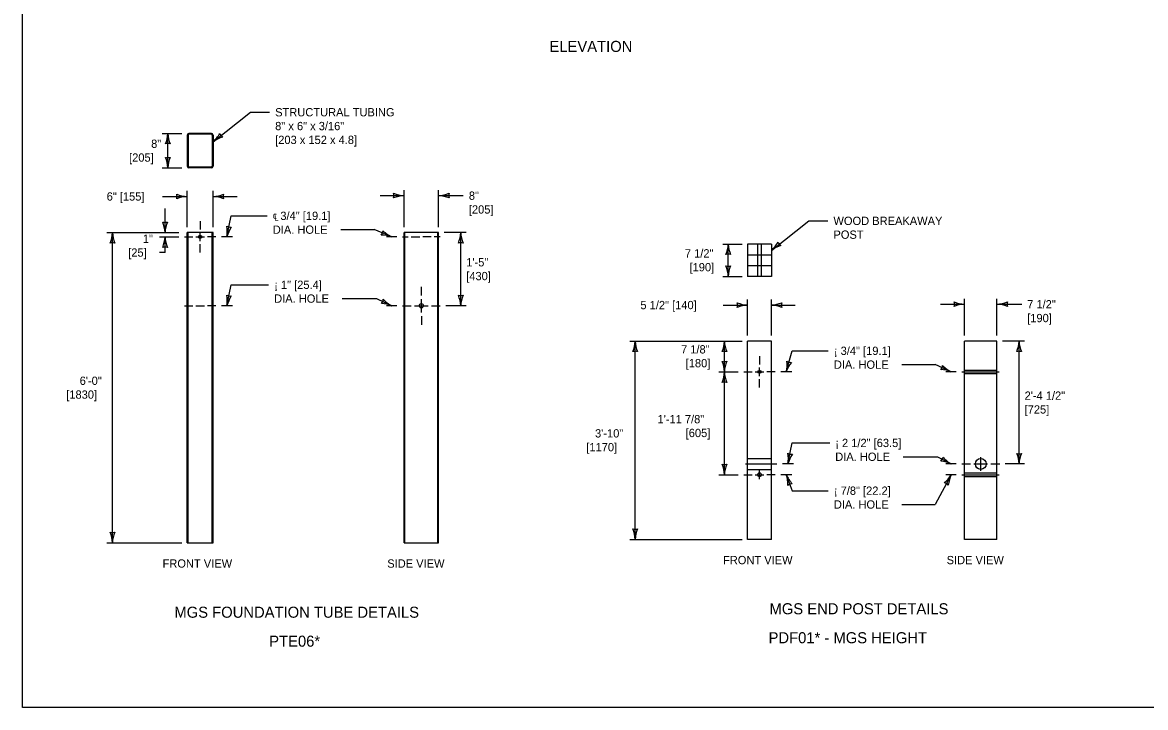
# Model space of a CAD drawing. Extents: x 49991.4 to 50021, y 49987.6 to 50011.4.
# Drawn here: x 49999.38 to 50007.52, y 49987.8 to 49992.76 of the extents above; entities that cross this region are included whole.
import ezdxf

# ---------------------------------------------------------------- set-up
doc = ezdxf.new("R2010")
doc.units = 0
for name, color, linetype in [('Level 1', 7, 'Continuous'), ('Level 2', 7, 'Continuous'), ('Level 3', 7, 'Continuous'), ('Level 4', 7, 'Continuous'), ('Level 5', 7, 'Continuous')]:
    doc.layers.add(name, color=color, linetype=linetype)

msp = doc.modelspace()

# ---------------------------------------------------------------- linework, layer by layer
at = {"layer": 'Level 1'}
for p, q in [((50000.7519, 49991.9559), (50000.5881, 49991.9559)), ((50000.5764, 49991.9442), (50000.5764, 49991.718)), ((50000.5822, 49991.9442), (50000.5822, 49991.718)), ((50000.7519, 49991.95), (50000.5881, 49991.95)), ((50000.7577, 49991.9442), (50000.7577, 49991.718)), ((50000.7636, 49991.9442), (50000.7636, 49991.718)), ((50000.7519, 49991.7121), (50000.5881, 49991.7121)), ((50000.7519, 49991.7063), (50000.5881, 49991.7063)), ((50000.5764, 49988.9916), (50000.5764, 49991.238)), ((50000.7636, 49991.238), (50000.5764, 49991.238)), ((50000.7636, 49988.9916), (50000.7636, 49991.238)), ((50002.147, 49988.9916), (50002.147, 49991.238)), ((50002.3966, 49991.238), (50002.147, 49991.238)), ((50002.3966, 49988.9916), (50002.3966, 49991.238)), ((50004.6346, 49991.1545), (50004.6346, 49990.9201)), ((50004.8062, 49991.1545), (50004.6346, 49991.1545)), ((50004.8062, 49991.1545), (50004.8062, 49990.9201)), ((50004.8062, 49990.9201), (50004.6346, 49990.9201)), ((50004.6346, 49989.0165), (50004.6346, 49990.4517)), ((50004.8062, 49990.4517), (50004.6346, 49990.4517)), ((50004.8062, 49989.0165), (50004.8062, 49990.4517)), ((50006.2052, 49989.0165), (50006.2052, 49990.4517)), ((50006.4396, 49990.4517), (50006.2052, 49990.4517)), ((50006.4396, 49989.0165), (50006.4396, 49990.4517)), ((50000.5764, 49988.9916), (50000.7636, 49988.9916)), ((50002.147, 49988.9916), (50002.3966, 49988.9916)), ((50004.8062, 49989.0165), (50004.6346, 49989.0165)), ((50006.4396, 49989.0165), (50006.2052, 49989.0165))]:
    msp.add_line(p, q, dxfattribs=at)
msp.add_lwpolyline([(49999.3835, 49998.9992), (50016.7501, 49998.9992), (50016.7501, 49987.7988), (49999.3835, 49987.7988)], close=True, dxfattribs=at)
for centre, radius in [((50000.67, 49991.2068), 0.0117), ((50002.2718, 49990.7076), 0.0156), ((50004.7204, 49990.2294), 0.0117), ((50006.3224, 49989.5625), 0.039), ((50004.7204, 49989.4845), 0.0136)]:
    msp.add_circle(centre, radius, dxfattribs=at)
for centre, radius, start, end in [((50000.5881, 49991.9442), 0.0117, 90, 180), ((50000.7519, 49991.9442), 0.0117, 0, 90), ((50000.5881, 49991.9442), 0.00585, 90, 180), ((50000.7519, 49991.9442), 0.00585, 0, 90), ((50000.5881, 49991.718), 0.0117, 180, 270), ((50000.5881, 49991.718), 0.00585, 180, 270), ((50000.7519, 49991.718), 0.0117, 270, 0), ((50000.7519, 49991.718), 0.00585, 270, 0)]:
    msp.add_arc(centre, radius, start, end, dxfattribs=at)
at = {"layer": 'Level 3'}
for p, q in [((50000.7636, 49991.8948), (50001.0338, 49992.1091)), ((50001.0338, 49992.1091), (50001.1732, 49992.1091)), ((50000.396, 49991.9559), (50000.5364, 49991.9559)), ((50000.436, 49991.7063), (50000.436, 49991.9559)), ((50000.396, 49991.7063), (50000.5364, 49991.7063)), ((50000.3982, 49991.4993), (50000.5764, 49991.4993)), ((50000.5764, 49991.278), (50000.5764, 49991.5393)), ((50000.7636, 49991.278), (50000.7636, 49991.5393)), ((50000.7636, 49991.4993), (50000.937, 49991.4993)), ((50001.9735, 49991.5052), (50002.147, 49991.5052)), ((50002.147, 49991.278), (50002.147, 49991.5452)), ((50002.3966, 49991.278), (50002.3966, 49991.5452)), ((50002.3966, 49991.5052), (50002.5758, 49991.5052)), ((50000.4159, 49991.238), (50000.4159, 49991.4114)), ((50000.864, 49991.2068), (50000.8954, 49991.359)), ((50000.8954, 49991.359), (50001.156, 49991.359)), ((50004.8062, 49991.1085), (50005.0764, 49991.3228)), ((50005.0764, 49991.3228), (50005.2158, 49991.3228)), ((49999.9949, 49991.238), (50000.5163, 49991.238)), ((50000.0349, 49988.9916), (50000.0349, 49991.238)), ((50001.6887, 49991.259), (50001.9298, 49991.259)), ((50002.0583, 49991.2068), (50001.9298, 49991.259)), ((50002.5969, 49991.238), (50002.4366, 49991.238)), ((50002.5569, 49990.7076), (50002.5569, 49991.238)), ((50000.3759, 49991.2068), (50000.5163, 49991.2068)), ((50000.4159, 49991.0933), (50000.4159, 49991.2068)), ((50000.904, 49991.2068), (50000.8237, 49991.2068)), ((50002.0946, 49991.2068), (50002.0183, 49991.2068)), ((50004.4542, 49991.1545), (50004.5946, 49991.1545)), ((50004.4942, 49990.9201), (50004.4942, 49991.1545)), ((50000.4159, 49991.0933), (50000.3759, 49991.0933)), ((50004.4542, 49990.9201), (50004.5946, 49990.9201)), ((50000.8641, 49990.7076), (50000.8955, 49990.8598)), ((50000.8955, 49990.8598), (50001.1661, 49990.8598)), ((50004.6346, 49990.4917), (50004.6346, 49990.753)), ((50004.8062, 49990.4917), (50004.8062, 49990.753)), ((50006.2052, 49990.4917), (50006.2052, 49990.7589)), ((50006.4396, 49990.4917), (50006.4396, 49990.7589)), ((50000.9041, 49990.7076), (50000.8237, 49990.7076)), ((50002.0947, 49990.7076), (50002.0184, 49990.7076)), ((50002.5969, 49990.7076), (50002.4489, 49990.7076)), ((50004.4564, 49990.713), (50004.6346, 49990.713)), ((50004.8062, 49990.713), (50004.9796, 49990.713)), ((50006.0318, 49990.7189), (50006.2052, 49990.7189)), ((50006.4396, 49990.7189), (50006.6188, 49990.7189)), ((50003.7803, 49990.4517), (50004.5946, 49990.4517)), ((50003.8203, 49989.0165), (50003.8203, 49990.4517)), ((50004.4663, 49990.2294), (50004.4663, 49990.4517)), ((50006.6399, 49990.4517), (50006.4796, 49990.4517)), ((50006.5999, 49989.5625), (50006.5999, 49990.4517)), ((50004.9144, 49990.2294), (50004.958, 49990.3816)), ((50004.958, 49990.3816), (50005.2187, 49990.3816)), ((50005.7513, 49990.2816), (50005.9924, 49990.2816)), ((50006.109, 49990.2294), (50005.9924, 49990.2816)), ((50004.4263, 49990.2294), (50004.5667, 49990.2294)), ((50004.4663, 49989.4845), (50004.4663, 49990.2294)), ((50004.9544, 49990.2294), (50004.8741, 49990.2294)), ((50006.1453, 49990.2294), (50006.069, 49990.2294)), ((50004.9266, 49989.5625), (50004.958, 49989.7147)), ((50004.958, 49989.7147), (50005.2287, 49989.7147)), ((50004.9666, 49989.5625), (50004.8862, 49989.5625)), ((50006.1453, 49989.5625), (50006.069, 49989.5625)), ((50006.6399, 49989.5625), (50006.4995, 49989.5625)), ((50004.4263, 49989.4845), (50004.5667, 49989.4845)), ((50004.9544, 49989.4845), (50004.8741, 49989.4845)), ((50004.9144, 49989.4845), (50004.958, 49989.369)), ((50006.109, 49989.4845), (50005.9924, 49989.269)), ((50006.1453, 49989.4845), (50006.069, 49989.4845)), ((50004.958, 49989.369), (50005.2187, 49989.369)), ((50005.7513, 49989.269), (50005.9924, 49989.269)), ((49999.9949, 49988.9916), (50000.5364, 49988.9916)), ((50003.7803, 49989.0165), (50004.5946, 49989.0165))]:
    msp.add_line(p, q, dxfattribs=at)
for points in [[(50001.6988, 49990.7598), (50001.9459, 49990.7598), (50002.0584, 49990.7076)], [(50005.7613, 49989.6147), (50006.0085, 49989.6147), (50006.109, 49989.5625)]]:
    msp.add_lwpolyline(points, dxfattribs=at)
for centre, radius, start, end in [((50000.2138, 49991.9651), 0.2223, 337.45601, 357.63952), ((50000.6687, 49991.9674), 0.233, 182.82731, 202.07716), ((50000.6085, 49992.0687), 0.233, 311.72481, 330.97466), ((50000.8634, 49991.9753), 0.0548, 201.03631, 236.75867), ((50000.436, 49991.8277), 0.0548, 72.13882, 107.86118), ((50000.8959, 49991.7162), 0.2223, 106.35351, 126.53701), ((50000.436, 49991.8345), 0.0548, 252.13882, 287.86118), ((50000.2033, 49991.6948), 0.233, 2.82731, 22.07716), ((50000.6581, 49991.6971), 0.2223, 157.45601, 177.63952), ((50000.5855, 49991.7214), 0.2223, 247.45601, 267.63952), ((50000.4482, 49991.4993), 0.0548, 342.13882, 17.86118), ((50000.5879, 49991.2666), 0.233, 92.82731, 112.07716), ((50000.7521, 49991.732), 0.233, 272.82731, 292.07716), ((50000.7544, 49991.2771), 0.2223, 67.45601, 87.63952), ((50000.8918, 49991.4993), 0.0548, 162.13882, 197.86118), ((50002.1561, 49991.7273), 0.2223, 247.45601, 267.63952), ((50002.0188, 49991.5052), 0.0548, 342.13882, 17.86118), ((50002.1585, 49991.2725), 0.233, 92.82731, 112.07716), ((50002.3851, 49991.7379), 0.233, 272.82731, 292.07716), ((50002.3874, 49991.283), 0.2223, 67.45601, 87.63952), ((50002.5248, 49991.5052), 0.0548, 162.13882, 197.86118), ((50000.4159, 49991.3662), 0.0548, 252.13882, 287.86118), ((50000.1832, 49991.2265), 0.233, 2.82731, 22.07716), ((50000.638, 49991.2288), 0.2223, 157.45601, 177.63952), ((49999.8127, 49991.2471), 0.2223, 337.45601, 357.63952), ((50000.2676, 49991.2495), 0.233, 182.82731, 202.07716), ((50000.8899, 49991.3323), 0.0548, 240.46023, 276.18259), ((50000.6337, 49991.2426), 0.233, 351.14872, 10.39857), ((50001.0797, 49991.1528), 0.2223, 145.77742, 165.96093), ((50001.9396, 49991.255), 0.0548, 320.03811, 355.76047), ((50002.1565, 49991.4181), 0.233, 225.82213, 245.07198), ((50002.3242, 49991.2495), 0.233, 337.92284, 357.17269), ((50002.779, 49991.2471), 0.2223, 182.36048, 202.54399), ((50000.0349, 49991.1098), 0.0548, 72.13882, 107.86118), ((50000.1937, 49991.2159), 0.2223, 337.45601, 357.63952), ((50000.6486, 49991.2183), 0.233, 182.82731, 202.07716), ((50001.9833, 49990.9975), 0.2223, 70.25977, 90.44328), ((50002.5569, 49991.1098), 0.0548, 72.13882, 107.86118), ((50004.2721, 49991.1636), 0.2223, 337.45601, 357.63952), ((50004.7269, 49991.166), 0.233, 182.82731, 202.07716), ((50004.6511, 49991.2824), 0.233, 311.72481, 330.97466), ((50004.9386, 49990.9299), 0.2223, 106.35351, 126.53701), ((50004.906, 49991.189), 0.0548, 201.03631, 236.75867), ((50000.4159, 49991.0786), 0.0548, 72.13882, 107.86118), ((50004.4942, 49991.0262), 0.0548, 72.13882, 107.86118), ((50004.4942, 49991.0483), 0.0548, 252.13882, 287.86118), ((50004.2615, 49990.9086), 0.233, 2.82731, 22.07716), ((50004.7163, 49990.9109), 0.2223, 157.45601, 177.63952), ((50000.89, 49990.8331), 0.0548, 240.46023, 276.18259), ((50000.6338, 49990.7434), 0.233, 351.14872, 10.39857), ((50001.0797, 49990.6536), 0.2223, 145.77742, 165.96093), ((50001.9421, 49990.7615), 0.0548, 317.24943, 352.97179), ((50002.1602, 49990.9052), 0.2223, 222.56662, 242.75013), ((50002.3348, 49990.6984), 0.2223, 2.36048, 22.54399), ((50002.5569, 49990.8358), 0.0548, 252.13882, 287.86118), ((50002.7896, 49990.6961), 0.233, 157.92284, 177.17269), ((50006.2143, 49990.9411), 0.2223, 247.45601, 267.63952), ((50006.077, 49990.7189), 0.0548, 342.13882, 17.86118), ((50006.4281, 49990.9517), 0.233, 272.82731, 292.07716), ((50006.5678, 49990.7189), 0.0548, 162.13882, 197.86118), ((50001.9709, 49990.4916), 0.233, 67.93792, 87.18777), ((50004.6437, 49990.9352), 0.2223, 247.45601, 267.63952), ((50004.5064, 49990.713), 0.0548, 342.13882, 17.86118), ((50004.6461, 49990.4803), 0.233, 92.82731, 112.07716), ((50004.7947, 49990.9458), 0.233, 272.82731, 292.07716), ((50004.797, 49990.4909), 0.2223, 67.45601, 87.63952), ((50004.9344, 49990.713), 0.0548, 162.13882, 197.86118), ((50006.2167, 49990.4862), 0.233, 92.82731, 112.07716), ((50006.4304, 49990.4968), 0.2223, 67.45601, 87.63952), ((50003.5982, 49990.4609), 0.2223, 337.45601, 357.63952), ((50004.053, 49990.4632), 0.233, 182.82731, 202.07716), ((50004.2442, 49990.4609), 0.2223, 337.45601, 357.63952), ((50004.699, 49990.4632), 0.233, 182.82731, 202.07716), ((50006.3672, 49990.4632), 0.233, 337.92284, 357.17269), ((50006.8221, 49990.4609), 0.2223, 182.36048, 202.54399), ((50003.8203, 49990.3235), 0.0548, 72.13882, 107.86118), ((50004.4663, 49990.3235), 0.0548, 72.13882, 107.86118), ((50006.5999, 49990.3235), 0.0548, 72.13882, 107.86118), ((50004.4663, 49990.3576), 0.0548, 252.13882, 287.86118), ((50004.2336, 49990.2179), 0.233, 2.82731, 22.07716), ((50004.6884, 49990.2203), 0.2223, 157.45601, 177.63952), ((50004.6875, 49990.2825), 0.233, 346.84214, 6.09199), ((50005.1254, 49990.1595), 0.2223, 141.47084, 161.65435), ((50004.9497, 49990.3527), 0.0548, 236.15365, 271.87601), ((50005.992, 49990.2818), 0.0548, 318.01665, 353.73901), ((50006.2146, 49990.4371), 0.233, 223.80067, 243.05052), ((50004.2442, 49990.2386), 0.2223, 337.45601, 357.63952), ((50004.699, 49990.2409), 0.233, 182.82731, 202.07716), ((50006.0266, 49990.023), 0.2223, 68.23831, 88.42182), ((50004.4663, 49990.1012), 0.0548, 72.13882, 107.86118), ((50004.9525, 49989.6881), 0.0548, 240.46023, 276.18259), ((50004.6964, 49989.5984), 0.233, 351.14872, 10.39857), ((50005.1423, 49989.5086), 0.2223, 145.77742, 165.96093), ((50005.9952, 49989.6216), 0.0548, 314.69944, 350.4218), ((50006.2195, 49989.7555), 0.2223, 220.01663, 240.20014), ((50006.3778, 49989.5534), 0.2223, 2.36048, 22.54399), ((50006.5999, 49989.6907), 0.0548, 252.13882, 287.86118), ((50006.8326, 49989.551), 0.233, 157.92284, 177.17269), ((50004.4663, 49989.6127), 0.0548, 252.13882, 287.86118), ((50004.2336, 49989.473), 0.233, 2.82731, 22.07716), ((50004.6884, 49989.4754), 0.2223, 157.45601, 177.63952), ((50006.012, 49989.3507), 0.233, 65.38793, 84.63778), ((50004.7033, 49989.4147), 0.2223, 358.13456, 18.31807), ((50005.1281, 49989.5775), 0.233, 203.50586, 222.75571), ((50005.9098, 49989.6054), 0.233, 309.51357, 328.76342), ((50006.3087, 49989.3869), 0.2223, 153.95121, 174.13472), ((50004.9597, 49989.3646), 0.0548, 92.81737, 128.53973), ((50006.048, 49989.3718), 0.0548, 43.72955, 79.45191), ((50000.0349, 49989.1198), 0.0548, 252.13882, 287.86118), ((49999.8022, 49988.9801), 0.233, 2.82731, 22.07716), ((50000.257, 49988.9824), 0.2223, 157.45601, 177.63952), ((50003.8203, 49989.1447), 0.0548, 252.13882, 287.86118), ((50003.5876, 49989.005), 0.233, 2.82731, 22.07716), ((50004.0425, 49989.0074), 0.2223, 157.45601, 177.63952)]:
    msp.add_arc(centre, radius, start, end, dxfattribs=at)
at = {"layer": 'Level 4'}
for p, q in [((50000.6583, 49991.9559), (50000.6583, 49991.95)), ((50000.6817, 49991.9559), (50000.6817, 49991.95)), ((50000.5764, 49991.8467), (50000.5822, 49991.8467)), ((50000.5764, 49991.8155), (50000.5822, 49991.8155)), ((50000.7577, 49991.8467), (50000.7636, 49991.8467)), ((50000.7577, 49991.8155), (50000.7636, 49991.8155)), ((50000.6583, 49991.7121), (50000.6583, 49991.7063)), ((50000.6817, 49991.7121), (50000.6817, 49991.7063)), ((50000.5822, 49988.9916), (50000.5822, 49991.238)), ((50000.7577, 49988.9916), (50000.7577, 49991.238)), ((50002.1528, 49988.9916), (50002.1528, 49991.238)), ((50002.3907, 49988.9916), (50002.3907, 49991.238)), ((50002.147, 49991.2185), (50002.1528, 49991.2185)), ((50002.147, 49991.1951), (50002.1528, 49991.1951)), ((50002.3907, 49991.2185), (50002.3966, 49991.2185)), ((50002.3907, 49991.1951), (50002.3966, 49991.1951)), ((50004.7067, 49991.1545), (50004.7067, 49990.9201)), ((50004.734, 49990.9201), (50004.734, 49991.1545)), ((50004.6346, 49991.0763), (50004.8062, 49991.0763)), ((50004.6346, 49990.9983), (50004.8062, 49990.9983)), ((50000.5764, 49990.7232), (50000.5822, 49990.7232)), ((50000.5764, 49990.692), (50000.5822, 49990.692)), ((50000.7577, 49990.7232), (50000.7636, 49990.7232)), ((50000.7577, 49990.692), (50000.7636, 49990.692)), ((50006.2052, 49990.2411), (50006.4396, 49990.2411)), ((50006.2052, 49990.2177), (50006.4396, 49990.2177)), ((50004.6346, 49989.6015), (50004.8062, 49989.6015)), ((50004.6346, 49989.5235), (50004.8062, 49989.5235)), ((50006.2052, 49989.4982), (50006.4396, 49989.4982)), ((50006.2052, 49989.4709), (50006.4396, 49989.4709))]:
    msp.add_line(p, q, dxfattribs=at)
at = {"layer": 'Level 5'}
for p, q in [((50000.67, 49991.3205), (50000.6699, 49991.2605)), ((50000.67, 49991.1753), (50000.67, 49991.2383)), ((50000.5563, 49991.2068), (50000.6163, 49991.2068)), ((50000.6385, 49991.2068), (50000.7015, 49991.2068)), ((50000.67, 49991.0931), (50000.6699, 49991.1531)), ((50000.7837, 49991.2068), (50000.7236, 49991.2068)), ((50002.1346, 49991.2068), (50002.1755, 49991.2068)), ((50002.1977, 49991.2068), (50002.2607, 49991.2068)), ((50002.3429, 49991.2068), (50002.2828, 49991.2068)), ((50002.4089, 49991.2068), (50002.365, 49991.2068)), ((50002.2718, 49990.7817), (50002.2718, 49990.8447)), ((50002.2718, 49990.6584), (50002.2718, 49990.7567)), ((50000.5563, 49990.7076), (50000.6163, 49990.7076)), ((50000.6385, 49990.7076), (50000.7015, 49990.7076)), ((50000.7837, 49990.7076), (50000.7236, 49990.7076)), ((50002.1346, 49990.7076), (50002.1976, 49990.7076)), ((50002.2226, 49990.7076), (50002.3209, 49990.7076)), ((50002.3459, 49990.7076), (50002.4089, 49990.7076)), ((50002.2718, 49990.6334), (50002.2718, 49990.5704)), ((50004.7204, 49990.3431), (50004.7203, 49990.2831)), ((50004.7204, 49990.1979), (50004.7204, 49990.2609)), ((50004.6067, 49990.2294), (50004.6667, 49990.2294)), ((50004.6889, 49990.2294), (50004.7519, 49990.2294)), ((50004.7204, 49990.1157), (50004.7203, 49990.1757)), ((50004.8341, 49990.2294), (50004.774, 49990.2294)), ((50006.1853, 49990.2294), (50006.456, 49990.2294)), ((50006.3224, 49989.5134), (50006.3224, 49989.6117)), ((50004.6189, 49989.5625), (50004.8462, 49989.5625)), ((50004.7204, 49989.453), (50004.7204, 49989.516)), ((50006.1853, 49989.5625), (50006.2483, 49989.5625)), ((50006.2733, 49989.5625), (50006.3715, 49989.5625)), ((50006.3965, 49989.5625), (50006.4595, 49989.5625)), ((50004.6067, 49989.4845), (50004.6667, 49989.4845)), ((50004.6889, 49989.4845), (50004.7519, 49989.4845)), ((50004.8341, 49989.4845), (50004.774, 49989.4845)), ((50006.1853, 49989.4845), (50006.456, 49989.4845))]:
    msp.add_line(p, q, dxfattribs=at)

# ---------------------------------------------------------------- texts
at = {"layer": 'Level 2'}
for s, height, p in [('ELEVATION', 0.08, (50003.1993, 49992.5458)), ('STRUCTURAL TUBING ', 0.06, (50001.2132, 49992.0791)), ('8" x 6" x 3/16"', 0.06, (50001.2132, 49991.9791)), ('8"', 0.06, (50000.3153, 49991.8511)), ('[203 x 152 x 4.8]', 0.06, (50001.2132, 49991.8791)), ('[205]', 0.06, (50000.1555, 49991.7511)), ('6" [155]', 0.06, (49999.9932, 49991.4693)), ('8"', 0.06, (50002.6158, 49991.4752)), ('℄ 3/4" [19.1]', 0.06, (50001.196, 49991.329)), ('[205]', 0.06, (50002.6158, 49991.3752)), ('WOOD BREAKAWAY', 0.06, (50005.2558, 49991.2928)), ('1"', 0.06, (50000.2552, 49991.1633)), ('DIA. HOLE', 0.06, (50001.196, 49991.229)), ('POST', 0.06, (50005.2558, 49991.1928)), ('[25]', 0.06, (50000.1493, 49991.0633)), ('7 1/2"', 0.06, (50004.18, 49991.0573)), ('1\'-5"', 0.06, (50002.5969, 49990.9928)), ('[190]', 0.06, (50004.2138, 49990.9573)), ('[430]', 0.06, (50002.5969, 49990.8928)), ('¡ 1" [25.4]', 0.06, (50001.2061, 49990.8298)), ('DIA. HOLE', 0.06, (50001.2061, 49990.7298)), ('5 1/2" [140]', 0.06, (50003.858, 49990.683)), ('7 1/2"', 0.06, (50006.6588, 49990.6889)), ('[190]', 0.06, (50006.6588, 49990.5889)), ('7 1/8"', 0.06, (50004.1522, 49990.3624)), ('¡ 3/4" [19.1]', 0.06, (50005.2587, 49990.3516)), ('[180]', 0.06, (50004.1859, 49990.2624)), ('DIA. HOLE', 0.06, (50005.2587, 49990.2516)), ('6\'-0"', 0.06, (49999.7979, 49990.1348)), ('[1830]', 0.06, (49999.7006, 49990.0348)), ('2\'-4 1/2"', 0.06, (50006.6399, 49990.0271)), ('[725]', 0.06, (50006.6399, 49989.9271)), ('1\'-11 7/8"', 0.06, (50003.982, 49989.857)), ('3\'-10"', 0.06, (50003.5295, 49989.7541)), ('[605]', 0.06, (50004.1859, 49989.757)), (' [1170]', 0.06, (50003.444, 49989.6541)), ('¡ 2 1/2" [63.5]', 0.06, (50005.2687, 49989.6847)), ('DIA. HOLE', 0.06, (50005.2687, 49989.5847)), ('¡ 7/8" [22.2]', 0.06, (50005.2587, 49989.339)), ('DIA. HOLE', 0.06, (50005.2587, 49989.239)), ('FRONT VIEW', 0.06, (50000.398, 49988.8116)), ('SIDE VIEW', 0.06, (50002.025, 49988.8116)), ('FRONT VIEW', 0.06, (50004.4562, 49988.8365)), ('SIDE VIEW', 0.06, (50006.0754, 49988.8365)), ('MGS END POST DETAILS', 0.08, (50004.7927, 49988.474)), ('MGS FOUNDATION TUBE DETAILS', 0.08, (50000.4837, 49988.449)), ('PTE06*', 0.08, (50001.1703, 49988.2393)), ('PDF01* - MGS HEIGHT', 0.08, (50004.7861, 49988.2642))]:
    msp.add_text(s, height=height, dxfattribs=at).set_placement(p)

doc.saveas('drawing.dxf')
